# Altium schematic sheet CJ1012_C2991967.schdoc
size 127 x 101 mm
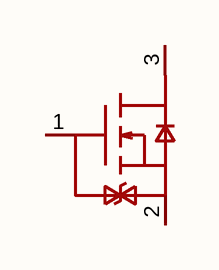
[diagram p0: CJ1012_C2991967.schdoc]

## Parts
Q?  cj1012  [SOT-523_L1.6-W0.8-P1.00-LS1.6-BR]  (value not drawn)

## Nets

Not connected (* = marked no-connect by the designer): Q? 1(G) 2(S) 3(D)

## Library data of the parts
Q? = cj1012: 数量:1个N沟道;漏源电压(Vdss):20V;连续漏极电流(Id):500mA;导通电阻(RDS(on)):700mΩ@4.5V;耗散功率(Pd):150mW;阈值电压(Vgs(th)):1.2V;; Manufacturer: CJ(江苏长电/长晶); Symbol: CJ1012_C2991967; AddInBom: yes; ModelId: 62a5eee6cc7e4598b9d48d5786c7bda6; ModelName: SOT-523_L1.6-W0.8-H0.2-P0.50-BL; ModelTransform: 62.992,62.992,0,270,0,0,0,0,0; Number: 1个N沟道; Drain to Source Voltage: 20V; Current - Continuous Drain(Id): 500mA; Pd - Power Dissipation: 150mW; Gate Threshold Voltage (Vgs(th)): 1.2V; Gate Charge(Qg): 750pC@4.5V; Input Capacitance(Ciss): 100pF; Reverse Transfer Capacitance (Crss@Vds): 12pF; Type: N沟道; Output Capacitance(Coss): 16pF; Vgs: ±12V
